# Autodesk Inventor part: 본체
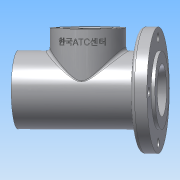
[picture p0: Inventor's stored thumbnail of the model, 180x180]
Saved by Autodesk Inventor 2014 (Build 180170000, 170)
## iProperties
Created: 2016-08
Part Number: 본체
Material: 알루미늄 6061
Document SubType Name: Modeling
Designer: 703
Density: 2.71 g/cm^3
Appearance: 알루미늄 - 평지
Mass: 815.238 g
Surface Area: 650.923 cm^2
Volume: 300.826 cm^3
Author: 703
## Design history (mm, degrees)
sketch "스케치1"
  geometry: C1 r 31 at (0, 0); 1 further point
  constraints: 1 centre point, 1 coincident
  dimensions: "d0" = 62 diameter of C1
extrude "돌출1" new body sketch "스케치1" stored distance "d1" = 99; taper "d2" = 0 deg
node "작업 평면1"
sketch "스케치2"
  geometry: L1 (31, 49.5)-(-31, 49.5) reference; C1 r 30 at (0, -6.5); 1 further point
  constraints: 1 centre point, 1 vertical alignment
  dimensions: "d4" = 56 distance from line of L1 C1.centre; "d5" = 60 diameter of C1
extrude "돌출2" join sketch "스케치2" stored distance "d6" = 102; taper "d7" = 0 deg
sketch "스케치3"
  geometry: C1 r 31 at (0, 0) reference; C2 r 50 at (0, 0)
  constraints: 1 centre point, 1 coincident
  dimensions: "d8" = 100 diameter of C2
extrude "돌출3" join sketch "스케치3" distance "d9" = 13; taper "d10" = 0 deg
node "작업 평면2"
node "작업 평면4"
sketch "스케치14"
  geometry: C1 r 26 at (0, 0); 1 further point
  constraints: 1 centre point, 1 coincident
  dimensions: "d37" = 52 diameter of C1
extrude "돌출9" cut sketch "스케치14" stored distance "d38" = 38; taper "d39" = 0 deg
sketch "스케치16"
  geometry: C1 r 30 at (0, 0) reference; C2 r 19 at (0, 0); 1 further point
  constraints: 1 centre point, 1 coincident
  dimensions: "d49" = 38 diameter of C2
extrude "돌출10" cut sketch "스케치16" stored distance "d50" = 38; taper "d51" = 0 deg
sketch "스케치17" dims "d52" = 48
  geometry: C1 r 19 at (0, 0) reference; C2 r 30 at (0, 0) reference; 3 further points
  constraints: 2 horizontal alignment, 1 coincident, 2 other
hole "구멍1" sketch "스케치17" at (-24, 0) diameter "d53" = 3.242; stored, may be unused: countersink angle "d57" = 90 deg, drill point angle "d59" = 118 deg; dims "d54" = 8, "d55" = 4, "d56" = 2, "d58" = 10
sketch "스케치19"
  geometry: C1 r 50 at (0, 0) reference; C2 r 31 at (0, 0)
  constraints: 1 centre point, 1 coincident
  dimensions: "d76" = 62 diameter of C2
extrude "돌출11" join sketch "스케치19" distance "d77" = 3; taper "d78" = 0 deg
node "작업 평면6"
sketch "스케치23"
  geometry: C1 r 16 at (0, 0); 1 further point
  constraints: 1 centre point, 1 coincident
  dimensions: "d87" = 32 diameter of C1
sketch "스케치24"
  geometry: C1 r 31 at (0, 0) reference; C2 r 21 at (0, 0)
  constraints: 1 centre point, 1 coincident
  dimensions: "d88" = 42 diameter of C2
feature "로프트3" sketch "스케치23", "스케치24" dims "d89" = 0, "d90" = 90 deg, "d91" = 0, "d92" = 90 deg
sketch "스케치25"
  geometry: L1 (0, 57.5)-(0, -57.5); L2 (-16, -51.5)-(16, -51.5) reference; L3 (12.5, -51.5)-(12.5, -44.2); L4 (12.5, -44.2)-(10, -44.2); L5 (10, -44.2)-(10, -41.5); L6 (10, -41.5)-(16.5, -41.5); L7 (16.5, -41.5)-(16.5, -36.5); L8 (16.5, -36.5)-(17.5, -36.5); L9 (17.5, -36.5)-(17.5, -25.5); L10 (-26, -25.5)-(26, -25.5) reference; L11 (21, -65.5)-(-21, -65.5) reference; L12 (17.5, -25.5)-(0, -25.5); L13 (0, -25.5)-(0, -51.5); L14 (12.5, -51.5)-(0, -51.5); 2 further points
  constraints: 22 end point, 5 parallel, 3 midpoint, 2 perpendicular, 2 point on line, 1 coincident, 1 collinear, 1 vertical
  dimensions: "d93" = 115 distance of L1.start L1.end; "d94" = 35 diameter of L9 L1; "d95" = 33 diameter of L7 L1; "d96" = 20 diameter of L5 L1; "d98" = 7.3 distance of L3.start L3.end; "d99" = 2.7 distance of L4.end L5.end; "d102" = 5 distance of L6.end L7.end; "d159" = 25 diameter of L3 L1
revolve "회전3" sketch "스케치25" stored, may be unused: angle "d103" = 90 deg
fillet "모깎기1" dims "d104" = 3
chamfer "모따기2" distance "d109" = 0.7; stored, may be unused: second distance "d110" = 2, angle "d111" = 30 deg
fillet "모깎기3" dims "d112" = 0.3
fillet "모깎기5" dims "d114" = 3
fillet "모깎기7" dims "d116" = 3
fillet "모깎기8" dims "d117" = 0.3
sketch "스케치27"
  geometry: L1 (0, 57.5)-(0, -57.5); L2 (21.138, 12.5)-(-23, 12.5) reference; L3 (17.5, 12.5)-(17.5, 23.5); L4 (17.5, 23.5)-(18.5, 23.5); L5 (18.5, 23.5)-(18.5, 25.25); L6 (18.5, 25.25)-(17.5, 25.25); L7 (17.5, 25.25)-(17.5, 28.5); L8 (17.5, 28.5)-(20, 28.5); L9 (20, 28.5)-(20, 37.5); L10 (20, 37.5)-(24, 37.5); L11 (24, 37.5)-(24, 40.5); L12 (24, 40.5)-(0, 40.5); L13 (0, 40.5)-(0, 12.5); L14 (0, 12.5)-(17.5, 12.5); L15 (31, 49.5)-(-31, 49.5) reference; 2 further points
  constraints: 26 end point, 6 parallel, 4 point on line, 3 perpendicular, 2 collinear, 1 coincident, 1 midpoint, 1 vertical, 1 vertical alignment
  dimensions: "d118" = 115 distance of L1.start L1.end; "d119" = 12 distance between parallel lines of L10 L15; "d120" = 21 distance between parallel lines of L8 L15; "d121" = 26 distance between parallel lines of L15 L4; "d123" = 35 diameter of L3 L1; "d124" = 1.75 distance of L4.end L5.end; "d125" = 37 diameter of L5 L1; "d126" = 3 distance of L10.end L11.end; "d127" = 48 diameter of L11 L1; "d128" = 40 diameter of L9 L1
revolve "회전4" sketch "스케치27" stored, may be unused: angle "d129" = 90 deg
sketch "스케치28" dims "d130" = 83
  geometry: C1 r 50 at (0, 0) reference; C2 r 31 at (0, 0) reference; C3 r 4 at (0, 41.5); 2 further points
  constraints: 2 coincident, 2 vertical alignment, 1 centre point, 2 other
  dimensions: "d132" = 8 diameter of C3
extrude "돌출12" cut sketch "스케치28" stored distance "d133" = 3; taper "d134" = 0 deg
chamfer "모따기3" distance "d138" = 1; stored, may be unused: second distance "d139" = 2, angle "d140" = 30 deg
fillet "모깎기9" dims "d141" = 3
node "작업 평면7"
sketch "스케치29"
  geometry: L1 (-18, 56)-(-80, 56) reference; L2 (0, 30)-(0, -30) reference; 2 further points
  constraints: 1 other
  dimensions: "d142" = 56 distance from line of L1 point (-10, 0); "d143" = 10 distance from line of L2 point (-10, 0)
feature "엠보싱1" sketch "스케치29" dims "d0" = 62, "d144" = 0.5, "d145" = 0
fillet "모깎기10" dims "d146" = 3
node "작업 평면8"
hole "구멍2" diameter "d151" = 40.376; stored, may be unused: countersink angle "d155" = 90 deg, drill point angle "d157" = 0 deg; dims "d149" = 10, "d150" = 10, "d152" = 42, "d153" = 4, "d154" = 2, "d156" = 9
fillet "모깎기11" dims "d158" = 0.3
node "솔리드1"
pattern_circular "원형 패턴1" dims angle "d61" = 360 deg
pattern_circular "원형 패턴2" dims angle "d136" = 360 deg
other parameters: "d3" = 49, "d15" = -14, "d36" = -56, "d86" = -14, "d147" = -9
